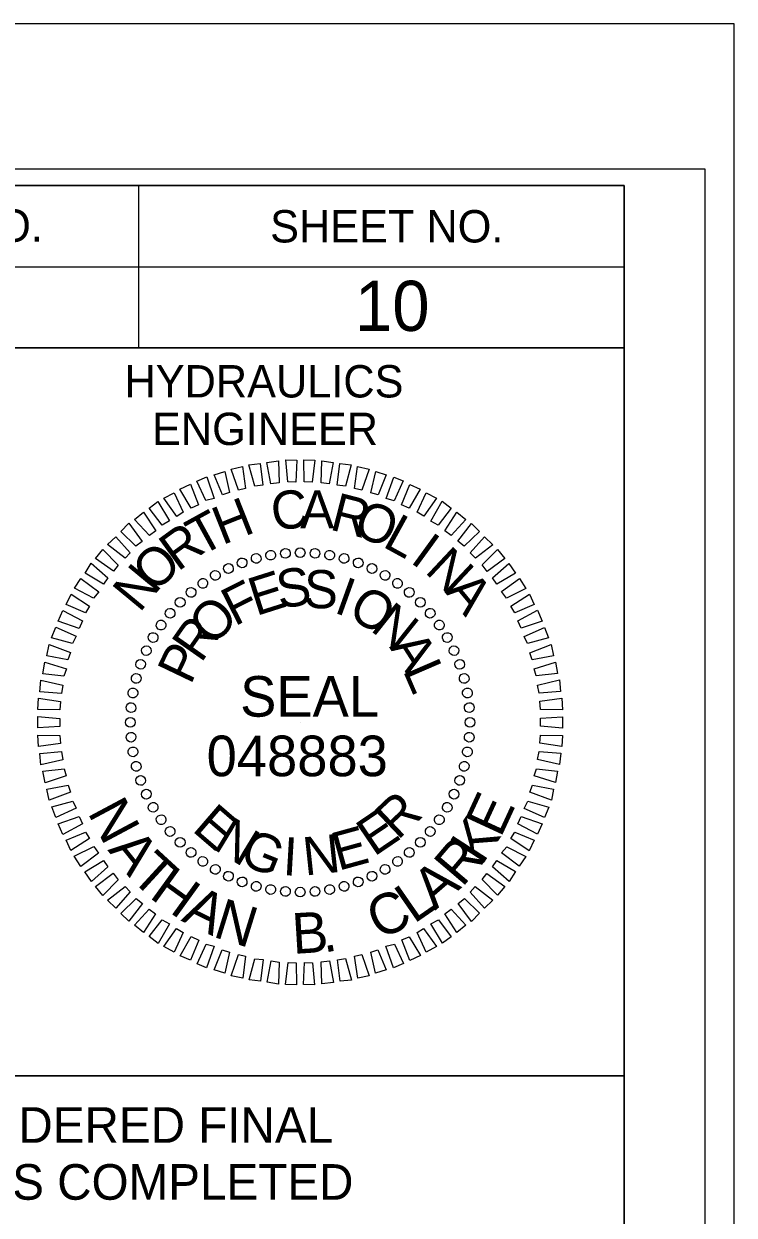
# Model space of a CAD drawing. Extents: x 1648649 to 1651827, y 844691 to 845879.
# Drawn here: x 1651536.5 to 1651646.3, y 845606.9 to 845791 of the extents above; entities that cross this region are included whole.
import ezdxf

# ---------------------------------------------------------------- set-up
doc = ezdxf.new("R2010")
doc.units = 0
for name, color, linetype in [('Default', 7, 'Continuous'), ('Old_Level_2', 7, 'Continuous'), ('Sheet Cutting Line CELL', 7, 'Continuous'), ('Sheet Data Field CELL', 7, 'Continuous'), ('Sheet Plot Border Inside CELL', 7, 'Continuous'), ('Sheet Plot Border Outside CELL', 7, 'Continuous'), ('Sheet Profile CELL', 7, 'Continuous'), ('Sheet Sticker Exception Certification CELL', 7, 'Continuous')]:
    doc.layers.add(name, color=color, linetype=linetype)

msp = doc.modelspace()

# ---------------------------------------------------------------- linework, layer by layer
at = {"layer": 'Old_Level_2'}
for p, q in [((1651572.41, 845708.44), (1651572.41, 845708.44)), ((1651574.7, 845708.89), (1651574.7, 845708.89)), ((1651576.94, 845709.25), (1651576.94, 845709.25)), ((1651579.24, 845709.34), (1651579.24, 845709.34)), ((1651581.55, 845709.22), (1651581.55, 845709.22)), ((1651583.8, 845708.9), (1651583.8, 845708.9)), ((1651586.01, 845708.46), (1651586.01, 845708.46)), ((1651568.15, 845706.9), (1651568.15, 845706.9)), ((1651570.22, 845707.77), (1651570.22, 845707.77)), ((1651588.21, 845707.77), (1651588.21, 845707.77)), ((1651590.32, 845706.87), (1651590.32, 845706.87)), ((1651564.16, 845704.58), (1651564.16, 845704.58)), ((1651566.13, 845705.82), (1651566.13, 845705.82)), ((1651592.38, 845705.86), (1651592.38, 845705.86)), ((1651594.28, 845704.58), (1651594.28, 845704.58)), ((1651562.35, 845703.24), (1651562.35, 845703.24)), ((1651596.14, 845703.2), (1651596.14, 845703.2)), ((1651560.66, 845701.64), (1651560.66, 845701.64)), ((1651597.79, 845701.66), (1651597.79, 845701.66)), ((1651559.12, 845699.99), (1651559.12, 845699.99)), ((1651599.38, 845699.96), (1651599.38, 845699.96)), ((1651557.74, 845698.14), (1651557.74, 845698.14)), ((1651600.72, 845698.16), (1651600.72, 845698.16)), ((1651556.46, 845696.23), (1651556.46, 845696.23)), ((1651601.96, 845696.19), (1651601.96, 845696.19)), ((1651555.45, 845694.18), (1651555.45, 845694.18)), ((1651603.04, 845694.17), (1651603.04, 845694.17)), ((1651554.55, 845692.07), (1651554.55, 845692.07)), ((1651603.91, 845692.09), (1651603.91, 845692.09)), ((1651553.85, 845689.86), (1651553.85, 845689.86)), ((1651604.58, 845689.91), (1651604.58, 845689.91)), ((1651553.42, 845687.66), (1651553.42, 845687.66)), ((1651605.04, 845687.62), (1651605.04, 845687.62)), ((1651553.1, 845685.4), (1651553.1, 845685.4)), ((1651605.39, 845685.37), (1651605.39, 845685.37)), ((1651552.98, 845683.1), (1651552.98, 845683.1)), ((1651579.23, 845683.09), (1651579.23, 845683.09)), ((1651605.48, 845683.07), (1651605.48, 845683.07)), ((1651553.07, 845680.8), (1651553.07, 845680.8)), ((1651605.37, 845680.77), (1651605.37, 845680.77)), ((1651553.42, 845678.56), (1651553.42, 845678.56)), ((1651605.04, 845678.52), (1651605.04, 845678.52)), ((1651553.88, 845676.26), (1651553.88, 845676.26)), ((1651604.61, 845676.31), (1651604.61, 845676.31)), ((1651554.55, 845674.08), (1651554.55, 845674.08)), ((1651603.92, 845674.1), (1651603.92, 845674.1)), ((1651555.42, 845672), (1651555.42, 845672)), ((1651603.01, 845672), (1651603.01, 845672)), ((1651556.5, 845669.98), (1651556.5, 845669.98)), ((1651602, 845669.94), (1651602, 845669.94)), ((1651557.74, 845668.02), (1651557.74, 845668.02)), ((1651600.73, 845668.03), (1651600.73, 845668.03)), ((1651559.08, 845666.21), (1651559.08, 845666.21)), ((1651599.35, 845666.18), (1651599.35, 845666.18)), ((1651560.68, 845664.51), (1651560.68, 845664.51)), ((1651597.81, 845664.53), (1651597.81, 845664.53)), ((1651562.32, 845662.97), (1651562.32, 845662.97)), ((1651596.11, 845662.93), (1651596.11, 845662.93)), ((1651564.18, 845661.59), (1651564.18, 845661.59)), ((1651566.08, 845660.32), (1651566.08, 845660.32)), ((1651592.34, 845660.36), (1651592.34, 845660.36)), ((1651594.3, 845661.59), (1651594.3, 845661.59)), ((1651568.14, 845659.31), (1651568.14, 845659.31)), ((1651590.32, 845659.28), (1651590.32, 845659.28)), ((1651570.25, 845658.4), (1651570.25, 845658.4)), ((1651572.46, 845657.71), (1651572.46, 845657.71)), ((1651574.66, 845657.28), (1651574.66, 845657.28)), ((1651576.92, 845656.95), (1651576.92, 845656.95)), ((1651579.22, 845656.83), (1651579.22, 845656.83)), ((1651581.52, 845656.93), (1651581.52, 845656.93)), ((1651583.76, 845657.28), (1651583.76, 845657.28)), ((1651586.05, 845657.74), (1651586.05, 845657.74)), ((1651588.24, 845658.4), (1651588.24, 845658.4))]:
    msp.add_line(p, q, dxfattribs=at)
for points in [[(1651572.21, 845719.57), (1651571.32, 845722.9), (1651573.04, 845723.09), (1651573.47, 845719.75)], [(1651574.72, 845719.93), (1651574.08, 845723.26), (1651575.86, 845723.5), (1651575.97, 845720.11)], [(1651577.33, 845720.24), (1651577.01, 845723.63), (1651578.73, 845723.61), (1651578.58, 845720.21)], [(1651579.84, 845720.23), (1651579.78, 845723.63), (1651581.5, 845723.6), (1651581.09, 845720.2)], [(1651582.45, 845720.12), (1651582.6, 845723.52), (1651584.34, 845723.23), (1651583.71, 845719.93)], [(1651584.97, 845719.74), (1651585.38, 845723.1), (1651587.11, 845722.86), (1651586.23, 845719.61)], [(1651567.22, 845718.23), (1651565.96, 845721.34), (1651567.57, 845721.84), (1651568.31, 845718.61)], [(1651569.71, 845718.95), (1651568.56, 845722.23), (1651570.33, 845722.62), (1651570.81, 845719.23)], [(1651587.65, 845719.21), (1651588.11, 845722.62), (1651589.9, 845722.23), (1651588.75, 845718.97)], [(1651590.17, 845718.58), (1651590.9, 845721.83), (1651592.53, 845721.34), (1651591.27, 845718.23)], [(1651562.39, 845716.21), (1651560.66, 845719.11), (1651562.27, 845719.87), (1651563.53, 845716.7)], [(1651564.67, 845717.35), (1651563.26, 845720.36), (1651564.82, 845721.01), (1651565.97, 845717.68)], [(1651592.54, 845717.68), (1651593.68, 845720.99), (1651595.16, 845720.39), (1651593.75, 845717.33)], [(1651594.91, 845716.72), (1651596.16, 845719.83), (1651597.79, 845719.13), (1651596.07, 845716.17)], [(1651560.16, 845714.92), (1651558.18, 845717.71), (1651559.79, 845718.57), (1651561.15, 845715.56)], [(1651597.33, 845715.56), (1651598.69, 845718.57), (1651600.28, 845717.71), (1651598.34, 845714.95)], [(1651555.93, 845711.97), (1651553.63, 845714.44), (1651555.03, 845715.56), (1651556.91, 845712.66)], [(1651557.89, 845713.57), (1651555.9, 845716.2), (1651557.25, 845717.22), (1651559.02, 845714.22)], [(1651599.4, 845714.19), (1651601.17, 845717.25), (1651602.55, 845716.18), (1651600.56, 845713.58)], [(1651601.57, 845712.66), (1651603.45, 845715.57), (1651604.83, 845714.44), (1651602.57, 845711.94)], [(1651553.86, 845710.31), (1651551.52, 845712.57), (1651552.76, 845713.85), (1651554.84, 845711.06)], [(1651603.58, 845711.07), (1651605.68, 845713.83), (1651606.96, 845712.59), (1651604.59, 845710.3)], [(1651552.17, 845708.45), (1651549.47, 845710.55), (1651550.75, 845711.77), (1651552.99, 845709.3)], [(1651605.5, 845709.27), (1651607.7, 845711.77), (1651608.98, 845710.54), (1651606.3, 845708.45)], [(1651550.37, 845706.43), (1651547.62, 845708.42), (1651548.75, 845709.8), (1651551.09, 845707.38)], [(1651607.36, 845707.42), (1651609.72, 845709.82), (1651610.85, 845708.43), (1651608.11, 845706.39)], [(1651548.84, 845704.42), (1651545.99, 845706.14), (1651546.95, 845707.68), (1651549.5, 845705.42)], [(1651608.96, 845705.41), (1651611.49, 845707.65), (1651612.51, 845706.15), (1651609.61, 845704.43)], [(1651547.31, 845702.3), (1651544.35, 845703.81), (1651545.37, 845705.3), (1651548.13, 845703.25)], [(1651610.36, 845703.29), (1651613.1, 845705.33), (1651614.12, 845703.78), (1651611.11, 845702.26)], [(1651546.09, 845700.03), (1651543.09, 845701.28), (1651543.85, 845702.92), (1651546.7, 845701.03)], [(1651611.76, 845701.02), (1651614.66, 845702.9), (1651615.36, 845701.29), (1651612.41, 845700.03)], [(1651545.09, 845697.6), (1651541.83, 845698.75), (1651542.58, 845700.38), (1651545.59, 845698.76)], [(1651612.85, 845698.79), (1651615.9, 845700.41), (1651616.61, 845698.75), (1651613.39, 845697.65)], [(1651544.08, 845695.29), (1651540.83, 845696.17), (1651541.48, 845697.8), (1651544.64, 845696.39)], [(1651613.83, 845696.35), (1651616.99, 845697.76), (1651617.6, 845696.15), (1651614.37, 845695.26)], [(1651543.34, 845692.76), (1651540.09, 845693.39), (1651540.43, 845695.12), (1651543.74, 845693.87)], [(1651614.71, 845693.85), (1651618.03, 845695.11), (1651618.38, 845693.39), (1651615.09, 845692.76)], [(1651542.71, 845690.24), (1651539.46, 845690.6), (1651539.79, 845692.39), (1651543.11, 845691.35)], [(1651615.38, 845691.35), (1651618.66, 845692.4), (1651619, 845690.63), (1651615.71, 845690.26)], [(1651542.34, 845687.57), (1651538.99, 845687.82), (1651539.16, 845689.6), (1651542.58, 845688.83)], [(1651615.89, 845688.85), (1651619.28, 845689.64), (1651619.47, 845687.87), (1651616.13, 845687.6)], [(1651542.12, 845685.05), (1651538.72, 845685.1), (1651538.79, 845686.83), (1651542.2, 845686.31)], [(1651616.25, 845686.35), (1651619.64, 845686.82), (1651619.78, 845685.05), (1651616.38, 845685.09)], [(1651542.11, 845682.44), (1651538.72, 845682.22), (1651538.69, 845684), (1651542.09, 845683.69)], [(1651616.35, 845683.73), (1651619.75, 845683.95), (1651619.78, 845682.17), (1651616.37, 845682.48)], [(1651542.21, 845679.83), (1651538.82, 845679.35), (1651538.68, 845681.12), (1651542.08, 845681.08)], [(1651616.34, 845681.12), (1651619.74, 845681.07), (1651619.67, 845679.35), (1651616.26, 845679.86)], [(1651542.57, 845677.32), (1651539.18, 845676.53), (1651538.99, 845678.3), (1651542.34, 845678.57)], [(1651616.13, 845678.61), (1651619.48, 845678.35), (1651619.3, 845676.57), (1651615.89, 845677.35)], [(1651543.08, 845674.82), (1651539.81, 845673.77), (1651539.46, 845675.54), (1651542.75, 845675.91)], [(1651615.75, 845675.93), (1651619, 845675.57), (1651618.67, 845673.79), (1651615.36, 845674.83)], [(1651543.75, 845672.32), (1651540.43, 845671.06), (1651540.08, 845672.78), (1651543.37, 845673.41)], [(1651615.12, 845673.41), (1651618.37, 845672.79), (1651618.04, 845671.06), (1651614.72, 845672.31)], [(1651544.63, 845669.83), (1651541.47, 845668.41), (1651540.86, 845670.02), (1651544.09, 845670.92)], [(1651614.38, 845670.89), (1651617.64, 845670), (1651616.98, 845668.37), (1651613.82, 845669.78)], [(1651545.62, 845667.39), (1651542.56, 845665.76), (1651541.85, 845667.42), (1651545.07, 845668.53)], [(1651613.37, 845668.57), (1651616.64, 845667.42), (1651615.88, 845665.79), (1651612.87, 845667.41)], [(1651546.7, 845665.16), (1651543.81, 845663.28), (1651543.1, 845664.88), (1651546.06, 845666.14)], [(1651612.37, 845666.15), (1651615.37, 845664.89), (1651614.62, 845663.26), (1651611.76, 845665.14)], [(1651548.1, 845662.88), (1651545.37, 845660.84), (1651544.34, 845662.4), (1651547.35, 845663.91)], [(1651611.15, 845663.88), (1651614.11, 845662.36), (1651613.09, 845660.88), (1651610.33, 845662.92)], [(1651549.5, 845660.76), (1651546.97, 845658.52), (1651545.96, 845660.02), (1651548.85, 845661.74)], [(1651609.62, 845661.76), (1651612.48, 845660.03), (1651611.51, 845658.5), (1651608.96, 845660.75)], [(1651551.1, 845658.75), (1651548.74, 845656.35), (1651547.62, 845657.75), (1651550.35, 845659.78)], [(1651608.09, 845659.74), (1651610.84, 845657.75), (1651609.72, 845656.37), (1651607.37, 845658.79)], [(1651552.97, 845656.9), (1651550.76, 845654.4), (1651549.48, 845655.63), (1651552.17, 845657.72)], [(1651606.29, 845657.72), (1651609, 845655.63), (1651607.71, 845654.4), (1651605.47, 845656.87)], [(1651554.88, 845655.1), (1651552.78, 845652.35), (1651551.51, 845653.58), (1651553.87, 845655.87)], [(1651604.6, 845655.86), (1651606.94, 845653.6), (1651605.71, 845652.33), (1651603.62, 845655.12)], [(1651556.89, 845653.52), (1651555.01, 845650.61), (1651553.63, 845651.73), (1651555.89, 845654.23)], [(1651602.54, 845654.21), (1651604.83, 845651.74), (1651603.44, 845650.61), (1651601.56, 845653.51)], [(1651559.06, 845651.98), (1651557.29, 845648.92), (1651555.91, 845649.99), (1651557.9, 845652.59)], [(1651561.13, 845650.61), (1651559.77, 845647.6), (1651558.18, 845648.46), (1651560.12, 845651.22)], [(1651598.3, 845651.26), (1651600.28, 845648.47), (1651598.68, 845647.6), (1651597.32, 845650.61)], [(1651600.58, 845652.6), (1651602.56, 845649.97), (1651601.22, 845648.95), (1651599.44, 845651.96)], [(1651563.55, 845649.45), (1651562.3, 845646.34), (1651560.67, 845647.04), (1651562.39, 845650)], [(1651596.07, 845649.96), (1651597.8, 845647.06), (1651596.19, 845646.3), (1651594.93, 845649.47)], [(1651565.92, 845648.5), (1651564.78, 845645.18), (1651563.3, 845645.78), (1651564.72, 845648.84)], [(1651568.29, 845647.6), (1651567.57, 845644.34), (1651565.94, 845644.83), (1651567.19, 845647.94)], [(1651591.25, 845647.94), (1651592.5, 845644.83), (1651590.89, 845644.33), (1651590.15, 845647.56)], [(1651593.79, 845648.82), (1651595.2, 845645.82), (1651593.65, 845645.16), (1651592.49, 845648.49)], [(1651570.81, 845646.96), (1651570.35, 845643.55), (1651568.57, 845643.94), (1651569.71, 845647.2)], [(1651573.49, 845646.43), (1651573.08, 845643.08), (1651571.35, 845643.31), (1651572.23, 845646.57)], [(1651576.01, 845646.06), (1651575.86, 845642.65), (1651574.13, 845642.94), (1651574.75, 845646.24)], [(1651578.62, 845645.95), (1651578.68, 845642.55), (1651576.96, 845642.57), (1651577.37, 845645.98)], [(1651581.13, 845645.94), (1651581.46, 845642.54), (1651579.73, 845642.57), (1651579.88, 845645.97)], [(1651583.74, 845646.24), (1651584.38, 845642.91), (1651582.6, 845642.67), (1651582.49, 845646.07)], [(1651586.25, 845646.6), (1651587.14, 845643.27), (1651585.42, 845643.08), (1651585, 845646.42)], [(1651588.75, 845647.22), (1651589.9, 845643.95), (1651588.13, 845643.55), (1651587.65, 845646.94)]]:
    msp.add_lwpolyline(points, close=True, dxfattribs=at)
for centre, major_axis in [((1651576.95, 845709.21), (-0.066, 0.75)), ((1651579.23, 845709.31), (0, 0.753)), ((1651581.52, 845709.21), (0.066, 0.75)), ((1651570.26, 845707.73), (-0.258, 0.708)), ((1651572.44, 845708.42), (-0.195, 0.727)), ((1651574.68, 845708.92), (-0.131, 0.742)), ((1651583.79, 845708.92), (0.131, 0.742)), ((1651586.02, 845708.42), (0.195, 0.727)), ((1651588.2, 845707.73), (0.258, 0.708)), ((1651566.12, 845705.8), (-0.376, 0.652)), ((1651568.15, 845706.86), (-0.318, 0.682)), ((1651590.32, 845706.86), (0.318, 0.682)), ((1651592.35, 845705.8), (0.376, 0.652)), ((1651564.19, 845704.57), (-0.432, 0.617)), ((1651594.27, 845704.57), (0.432, 0.617)), ((1651562.37, 845703.18), (-0.484, 0.577)), ((1651596.09, 845703.18), (0.484, 0.577)), ((1651559.14, 845699.95), (-0.577, 0.484)), ((1651560.69, 845701.63), (-0.532, 0.532)), ((1651597.78, 845701.63), (0.532, 0.532)), ((1651599.32, 845699.95), (0.577, 0.484)), ((1651557.75, 845698.13), (-0.617, 0.432)), ((1651600.72, 845698.13), (0.617, 0.432)), ((1651556.52, 845696.2), (-0.652, 0.376)), ((1651601.95, 845696.2), (0.652, 0.376)), ((1651555.46, 845694.17), (-0.682, 0.318)), ((1651603, 845694.17), (0.682, 0.318)), ((1651554.59, 845692.06), (-0.708, 0.258)), ((1651603.88, 845692.06), (0.708, 0.258)), ((1651553.9, 845689.87), (-0.727, 0.195)), ((1651604.57, 845689.87), (0.727, 0.195)), ((1651553.4, 845687.64), (-0.742, 0.131)), ((1651605.06, 845687.64), (0.742, 0.131)), ((1651553.1, 845685.37), (-0.75, 0.066)), ((1651605.36, 845685.37), (0.75, 0.066)), ((1651553, 845683.09), (-0.753, 0)), ((1651605.46, 845683.09), (0.753, 0)), ((1651553.1, 845680.8), (-0.75, -0.066)), ((1651605.36, 845680.8), (0.75, -0.066)), ((1651553.4, 845678.53), (-0.742, -0.131)), ((1651605.06, 845678.53), (0.742, -0.131)), ((1651553.9, 845676.3), (-0.727, -0.195)), ((1651604.57, 845676.3), (0.727, -0.195)), ((1651554.59, 845674.12), (-0.708, -0.258)), ((1651603.88, 845674.12), (0.708, -0.258)), ((1651555.46, 845672), (-0.682, -0.318)), ((1651603, 845672), (0.682, -0.318)), ((1651556.52, 845669.97), (-0.652, -0.376)), ((1651601.95, 845669.97), (0.652, -0.376)), ((1651557.75, 845668.04), (-0.617, -0.432)), ((1651600.72, 845668.04), (0.617, -0.432)), ((1651559.14, 845666.23), (-0.577, -0.484)), ((1651599.32, 845666.23), (0.577, -0.484)), ((1651560.69, 845664.54), (-0.532, -0.532)), ((1651597.78, 845664.54), (0.532, -0.532)), ((1651562.37, 845662.99), (-0.484, -0.577)), ((1651564.19, 845661.6), (-0.432, -0.617)), ((1651594.27, 845661.6), (0.432, -0.617)), ((1651596.09, 845662.99), (0.484, -0.577)), ((1651566.12, 845660.37), (-0.376, -0.652)), ((1651592.35, 845660.37), (0.376, -0.652)), ((1651568.15, 845659.32), (-0.318, -0.682)), ((1651570.26, 845658.44), (-0.258, -0.708)), ((1651572.44, 845657.75), (-0.195, -0.727)), ((1651586.02, 845657.75), (0.195, -0.727)), ((1651588.2, 845658.44), (0.258, -0.708)), ((1651590.32, 845659.32), (0.318, -0.682)), ((1651574.68, 845657.26), (-0.131, -0.742)), ((1651576.95, 845656.96), (-0.066, -0.75)), ((1651579.23, 845656.86), (0, -0.753)), ((1651581.52, 845656.96), (0.066, -0.75)), ((1651583.79, 845657.26), (0.131, -0.742))]:
    msp.add_ellipse(centre, major_axis=major_axis, ratio=0.999708, dxfattribs=at)
at = {"layer": 'Sheet Cutting Line CELL'}
msp.add_line((1651646.28, 845791.02), (1649962.28, 845791.02), dxfattribs=at)
at = {"layer": 'Sheet Plot Border Inside CELL'}
msp.add_lwpolyline([(1649975.28, 844713.47), (1651641.78, 844713.47), (1651641.78, 845768.57), (1649975.28, 845768.57)], close=True, dxfattribs=at)
at = {"layer": 'Sheet Plot Border Outside CELL'}
msp.add_lwpolyline([(1649962.28, 844691.02), (1651646.28, 844691.02), (1651646.28, 845791.02), (1649962.28, 845791.02)], close=True, dxfattribs=at)
at = {"layer": 'Sheet Profile CELL'}
for p, q in [((1651554.28, 845765.97), (1651554.28, 845740.97)), ((1651429.23, 845753.47), (1651629.28, 845753.47))]:
    msp.add_line(p, q, dxfattribs=at)
for points in [[(1651629.28, 845766.02), (1650129.28, 845766.02), (1650129.28, 844716.02), (1651629.28, 844716.02)], [(1651429.23, 845766.02), (1651629.28, 845766.02), (1651629.28, 845740.97), (1651429.23, 845740.97)], [(1651529.28, 845740.97), (1651629.28, 845740.97), (1651629.28, 845628.47), (1651529.28, 845628.47)]]:
    msp.add_lwpolyline(points, close=True, dxfattribs=at)
at = {"layer": 'Sheet Sticker Exception Certification CELL'}
for p, q in [((1651429.23, 845628.47), (1651629.27, 845628.47)), ((1651429.23, 845628.47), (1651629.27, 845628.47)), ((1651629.27, 845628.46), (1651629.27, 845604.96)), ((1651629.27, 845628.46), (1651629.27, 845604.96))]:
    msp.add_line(p, q, dxfattribs=at)

# ---------------------------------------------------------------- texts
at = {"layer": 'Default'}
for s, rotation, p in [('N', 298.0773, (1651546.31, 845669.19)), ('E', 65.2198, (1651610.2, 845665.13)), ('K', 57.024, (1651607.33, 845660.9)), ('A', 308.6891, (1651549.42, 845663.36)), ('R', 49.6233, (1651604.25, 845657.47)), ('T', 317.4354, (1651552.76, 845659.05)), ('H', 324.1633, (1651555.75, 845656.11)), ('A', 40.877, (1651600.07, 845653.97)), ('A', 334.0411, (1651560.72, 845652.48)), ('C', 25.1886, (1651591.43, 845649.42)), ('L', 34.6689, (1651596.8, 845651.89)), ('N', 342.7874, (1651565.58, 845650.01)), ('B', 3.4911, (1651578.14, 845647.31)), ('.', 11.1059, (1651582.89, 845647.47))]:
    msp.add_text(s, height=6.27, rotation=rotation, dxfattribs=at).set_placement(p)
at = {"layer": 'Old_Level_2'}
for s, rotation, p in [('H', 21.6195, (1651567.2, 845710.44)), ('C', 7.2199, (1651575.11, 845712.67)), ('A', 0.0203, (1651579.23, 845713.05)), ('R', 345.6211, (1651583.63, 845712.92)), ('T', 28.8198, (1651563.83, 845708.65)), ('O', 338.4212, (1651587.14, 845712.2)), ('L', 331.2209, (1651591.78, 845710.34)), ('R', 36.0205, (1651560.31, 845706.29)), ('I', 324.0201, (1651596.06, 845707.91)), ('O', 43.2217, (1651556.76, 845702.99)), ('N', 316.8189, (1651598.33, 845706.33)), ('N', 50.4235, (1651554.41, 845699.91)), ('E', 17.6111, (1651572.41, 845699.49)), ('S', 8.2556, (1651576, 845700.65)), ('S', 358.9004, (1651579.76, 845700.77)), ('F', 26.967, (1651569.09, 845697.87)), ('I', 340.1896, (1651584.27, 845700.12)), ('A', 309.6172, (1651601.47, 845703.29)), ('O', 330.8335, (1651586.37, 845699.42)), ('O', 45.6812, (1651565.69, 845694.72)), ('N', 321.4766, (1651589.91, 845697.39)), ('R', 55.0397, (1651563.91, 845692.13)), ('P', 64.3989, (1651562.29, 845688.75)), ('A', 302.7603, (1651592.94, 845694.73)), ('L', 293.4009, (1651595.04, 845691.15)), ('R', 43.4814, (1651594.3, 845664.78)), ('E', 319.2769, (1651562.37, 845666.42)), ('E', 34.1241, (1651590.63, 845662.26)), ('N', 328.634, (1651565.56, 845663.65)), ('G', 337.9902, (1651569.57, 845661.37)), ('E', 15.4118, (1651585.12, 845660.13)), ('I', 356.7012, (1651576.45, 845659.5)), ('N', 6.0564, (1651579.96, 845659.41))]:
    msp.add_text(s, height=5.9, rotation=rotation, dxfattribs=at).set_placement(p)
for s, height, p in [('SEAL', 6.273, (1651569.96, 845683.97)), ('048883', 6.275, (1651564.78, 845674.77))]:
    msp.add_text(s, height=height, dxfattribs=at).set_placement(p)
at = {"layer": 'Sheet Data Field CELL'}
msp.add_text('10', height=7.75, dxfattribs=at).set_placement((1651587.7, 845743.57))
at = {"layer": 'Sheet Profile CELL'}
for s, height, p in [('PROJECT REFERENCE NO.', 5.0001, (1651451.44, 845757.34)), ('SHEET NO.', 5, (1651574.59, 845757.24)), ('HYDRAULICS', 5, (1651552.09, 845733.29)), ('ENGINEER', 5, (1651556.34, 845725.94))]:
    msp.add_text(s, height=height, dxfattribs=at).set_placement(p)
at = {"layer": 'Sheet Sticker Exception Certification CELL'}
for s, p in [('DOCUMENT NOT CONSIDERED FINAL', (1651450.3, 845618.13)), ('DOCUMENT NOT CONSIDERED FINAL', (1651450.3, 845618.13)), ('UNLESS ALL SIGNATURES COMPLETED', (1651445.23, 845609.33)), ('UNLESS ALL SIGNATURES COMPLETED', (1651445.23, 845609.33))]:
    msp.add_text(s, height=5.5, dxfattribs=at).set_placement(p)

doc.saveas('drawing.dxf')
